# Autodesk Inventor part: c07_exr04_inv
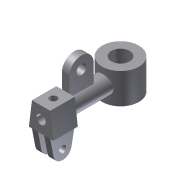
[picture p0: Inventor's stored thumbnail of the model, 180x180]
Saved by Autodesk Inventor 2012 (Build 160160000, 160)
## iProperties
Shininess: 77.0
Length Units: 11269
Angle Units: 11279
Time Units: 11290
Mass Units: 11283
Length Display Precision: 3
Angle Display Precision: 2
Created: 2001-12
Part Number: c07_exr04_inv
Document SubType Name: Modeling
Density: 1 g/cm^3
Material: Default
Density: 0.0
Volumn: 0.0
Area: 0.0
PropertySet Name: Model Information
Control State: 0
Master: False
Checked Out: False
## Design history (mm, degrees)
sketch "Sketch1"
  geometry: C1 r 30 at (0, 0)
  constraints: 1 centre point
  dimensions: "d0" = 60 diameter of C1
extrude "Extrusion1" new body sketch "Sketch1" stored distance "d1" = 50; taper "d2" = 0 deg
sketch "Sketch2"
  geometry: C1 r 15 at (0, 0)
  constraints: 1 centre point
  dimensions: "d3" = 30 diameter of C1
extrude "Extrusion2" join sketch "Sketch2" distance "d4" = 130; taper "d5" = 0 deg
sketch "Sketch3"
  geometry: L1 (-15, 20)-(-20, -20); L2 (-20, -20)-(20, -20); L3 (20, -20)-(15, 20); L4 (15, 20)-(-15, 20); C1 r 15 at (0, 0) reference
  constraints: 8 end point, 1 equal length, 1 horizontal, 1 parallel
  dimensions: "d6" = 40 distance of L1.end L2.end; "d7" = 30 distance of L3.end L1.start; "d8" = 20 distance from line of C1.centre L4; "d9" = 40 distance between parallel lines of L4 L2; "d10" = 20 horizontal distance of C1.centre L2.end
extrude "Extrusion3" join sketch "Sketch3" distance "d11" = 40; taper "d12" = 0 deg
sketch "Sketch4"
  geometry: L1 (-90, 44)-(-90, 10.92); L2 (-90, 10.92)-(-50, 10.92); L3 (-50, 10.92)-(-50, 44); L4 (-90, 20)-(-90, -20) reference; L5 (-130, 20)-(-90, 20) reference; C1 r 8 at (-70, 44); A1 r 20 centre (-70, 44) between (-50, 44) and (-90, 44)
  constraints: 6 end point, 2 centre point, 2 point on circle, 2 tangent, 1 coincident, 1 parallel, 1 perpendicular, 1 vertical
  dimensions: "d13" = 40 distance of L1.end L2.end; "d14" = 0 distance between parallel lines of L4 L1; "d15" = 24 distance from line of L5 A1.centre; "d16" = 16 diameter of C1
extrude "Extrusion4" join sketch "Sketch4" stored distance "d17" = 12; taper "d18" = 0 deg
sketch "Sketch5"
  geometry: L1 (-130, -20)-(-124.658, -47.828); L2 (-95.181, -47.753)-(-90, -20); L3 (-90, -20)-(-130, -20); L4 (-130, -20)-(-90, -20) reference; L5 (-90, 20)-(-90, -20) reference; L6 (-130, 20)-(-130, -20) reference; C1 r 6 at (-109.927, -45); A1 r 15 centre (-109.927, -45) between (-124.658, -47.828) and (-95.181, -47.753)
  constraints: 6 end point, 2 centre point, 2 collinear, 2 point on circle, 2 point on line, 2 tangent, 1 coincident, 1 horizontal
  dimensions: "d19" = 15 radius of A1; "d20" = 25 distance from line of L3 A1.centre; "d27" = 12 diameter of C1
extrude "Extrusion5" join sketch "Sketch5" stored distance "d21" = 30; taper "d22" = 0 deg
sketch "Sketch6"
  geometry: L1 (-5, -20)-(5, -20); L2 (5, -20)-(5, -78.834); L3 (5, -78.834)-(-5, -78.834); L4 (-5, -78.834)-(-5, -20); L5 (-15, -20)-(15, -20) reference; L6 (15, -47.828)-(15, -20) reference
  constraints: 8 end point, 2 parallel, 1 collinear, 1 horizontal, 1 perpendicular
  dimensions: "d23" = 10 distance of L2.end L3.end; "d24" = 10 distance between parallel lines of L6 L2
extrude "Extrusion6" cut sketch "Sketch6" distance "d25" = 40; taper "d26" = 0 deg
sketch "Sketch7"
  geometry: 1 further point
hole "Hole1" sketch "Sketch7" at (0, 0) diameter "d28" = 15; stored, may be unused: countersink angle "d32" = 82 deg, drill point angle "d34" = 0 deg; dims "d29" = 6, "d30" = 4, "d31" = 2, "d33" = 110
sketch "Sketch8"
  geometry: L1 (30, 0)-(0, 0) reference; L2 (30, 0)-(30, 40) reference; 1 further point
  dimensions: "d35" = 20 distance from line of L1 point (15, 20); "d36" = 15 distance from line of L2 point (15, 20)
hole "Hole2" sketch "Sketch8" at (15, 20) diameter "d37" = 12; stored, may be unused: countersink angle "d41" = 82 deg, drill point angle "d43" = 0 deg; dims "d38" = 6, "d39" = 4, "d40" = 2, "d42" = 8
sketch "Sketch9"
  geometry: C1 r 30 at (0, 0) reference
hole "Hole3" sketch "Sketch9" at (0, 0) diameter "d44" = 30; stored, may be unused: countersink angle "d48" = 82 deg, drill point angle "d50" = 0 deg; dims "d45" = 6, "d46" = 4, "d47" = 2, "d49" = 8
body "Solid1"
